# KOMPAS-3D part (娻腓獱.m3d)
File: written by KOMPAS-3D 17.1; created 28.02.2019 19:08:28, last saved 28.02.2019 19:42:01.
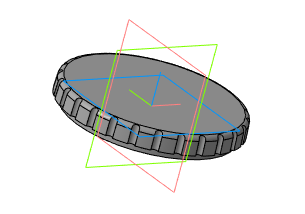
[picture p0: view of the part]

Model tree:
1. Эскиз:1
2. Элемент вращения:1
     Угол 1 = 360
3. Скругление:2
     Радиус = 2
4. Эскиз:2
5. Элемент вращения:2
     Угол 1 = 360
6. Массив по концентрической сетке:1  (with: Элемент вращения:2)  (26 pattern instances)
     Шаг 2 = 360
